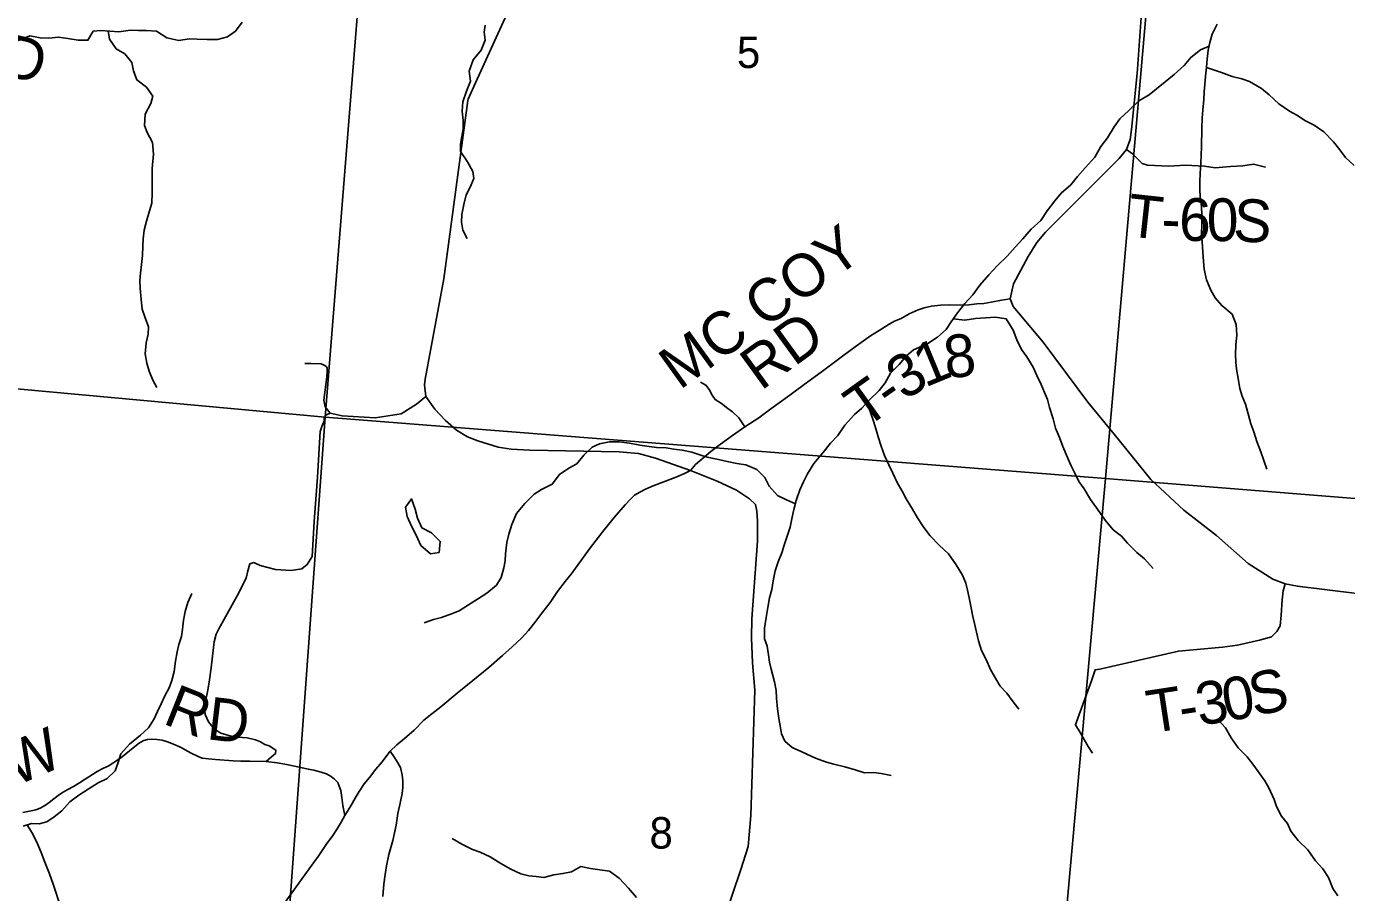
# Model space of a CAD drawing. Extents: x 0 to 42, y 0 to 22.
# Drawn here: x 2.271 to 3.149, y 15.878 to 16.454 of the extents above; entities that cross this region are included whole.
import ezdxf

# ---------------------------------------------------------------- set-up
doc = ezdxf.new("R2010")
doc.units = 0
for name, color, linetype in [('GM_X_County_Road', 7, 'Continuous'), ('GM_X_County_Road_Text', 7, 'Continuous'), ('GM_X_Minor_Lake', 7, 'Continuous'), ('GM_X_Minor_River', 7, 'Continuous'), ('GM_X_Section', 7, 'Continuous'), ('GM_X_Section_Text', 7, 'Continuous'), ('GM_X_Township_Road', 7, 'Continuous'), ('GM_X_Township_Road_Text', 7, 'Continuous'), ('GM_X_Unincorporated', 7, 'Continuous')]:
    doc.layers.add(name, color=color, linetype=linetype)

msp = doc.modelspace()

# ---------------------------------------------------------------- linework, layer by layer
at = {"layer": 'GM_X_County_Road'}
for points in [[(3.15556, 16.07734), (3.11596, 16.08209), (3.10775, 16.08373), (3.09954, 16.08683), (3.08329, 16.09723), (3.06213, 16.11584), (3.04041, 16.13263), (3.01849, 16.15304), (2.99402, 16.18319), (2.97659, 16.20462), (2.94677, 16.24432), (2.92682, 16.26806), (2.92495, 16.27329), (2.92703, 16.28318), (2.9369, 16.30146), (2.94257, 16.3107), (2.94845, 16.31763), (2.99745, 16.36645), (3.0023, 16.37263), (3.00466, 16.37925), (3.00554, 16.38588), (3.00939, 16.42316), (3.01821, 16.54744), (3.01914, 16.57163)], [(2.73394, 15.85903), (2.74582, 15.8937), (2.75074, 15.90912), (2.75254, 15.92978), (2.75503, 16.01291), (2.75344, 16.03129), (2.75281, 16.04777), (2.75312, 16.06045), (2.75693, 16.1121), (2.75685, 16.12533), (2.75653, 16.13198), (2.75558, 16.13642), (2.75146, 16.14022), (2.74291, 16.14593), (2.73008, 16.15195), (2.71233, 16.15915), (2.68905, 16.16732), (2.6778, 16.17033), (2.66481, 16.1716), (2.60551, 16.1727), (2.59308, 16.17332), (2.58439, 16.17456), (2.57093, 16.17871), (2.56409, 16.1814), (2.55664, 16.18595), (2.54937, 16.19225), (2.54217, 16.19996), (2.53637, 16.20835), (2.53544, 16.21601), (2.53591, 16.21985), (2.54815, 16.28662), (2.56429, 16.4051), (2.56443, 16.40592), (2.56825, 16.41433), (2.61413, 16.51522)]]:
    msp.add_lwpolyline(points, dxfattribs=at)
at = {"layer": 'GM_X_Minor_Lake'}
for points in [[(2.52524, 16.13798), (2.52287, 16.13473), (2.52379, 16.12848), (2.52679, 16.12202), (2.52998, 16.11557), (2.53299, 16.1093), (2.5394, 16.10378), (2.54526, 16.10452)], [(2.54526, 16.10452), (2.54586, 16.11191), (2.54002, 16.11761), (2.5336, 16.12105), (2.53078, 16.12731), (2.52929, 16.13338), (2.52686, 16.14021), (2.52524, 16.13798)]]:
    msp.add_lwpolyline(points, dxfattribs=at)
at = {"layer": 'GM_X_Minor_River'}
for points in [[(2.26547, 16.44498), (2.27284, 16.44813), (2.27983, 16.44678), (2.28551, 16.44657), (2.29194, 16.4473), (2.29818, 16.44633), (2.30517, 16.44517), (2.3116, 16.44515), (2.31503, 16.4512), (2.32014, 16.45174), (2.32619, 16.45134), (2.33205, 16.45075), (2.33981, 16.45186), (2.3453, 16.45165), (2.35021, 16.45163), (2.35721, 16.45123), (2.364, 16.44684), (2.37194, 16.44511), (2.37894, 16.44603), (2.38424, 16.44601), (2.39086, 16.44561), (2.39767, 16.44558), (2.4043, 16.44745), (2.4096, 16.45122), (2.41417, 16.45727)], [(2.57569, 16.45533), (2.57511, 16.4506), (2.57566, 16.44529), (2.57317, 16.43867), (2.56785, 16.43206), (2.56518, 16.42468), (2.5661, 16.41804), (2.56343, 16.41123), (2.56094, 16.40423), (2.56054, 16.39798), (2.56108, 16.39191), (2.56106, 16.38604), (2.56029, 16.38111), (2.55932, 16.37619), (2.5593, 16.37127), (2.56401, 16.36443), (2.56758, 16.35797), (2.56832, 16.35323), (2.56584, 16.34756), (2.56317, 16.34245), (2.56163, 16.33601), (2.56028, 16.32939), (2.56008, 16.32427), (2.56081, 16.31896), (2.56382, 16.31327)], [(3.06257, 16.45595), (3.05933, 16.44933), (3.05761, 16.44365), (3.05664, 16.43854), (3.05586, 16.43267), (3.05546, 16.42737), (3.05488, 16.42131), (3.05429, 16.41581), (3.05389, 16.41089), (3.05368, 16.40577), (3.05309, 16.39876), (3.0525, 16.39327), (3.05229, 16.38683), (3.05224, 16.37414), (3.05203, 16.36921), (3.05163, 16.36296), (3.05123, 16.35652), (3.05102, 16.35121), (3.051, 16.3461), (3.05136, 16.34098), (3.05209, 16.33454), (3.05245, 16.32904), (3.05243, 16.3226), (3.05222, 16.31634), (3.05257, 16.31104), (3.05312, 16.30459), (3.05347, 16.29815), (3.05402, 16.29303), (3.05551, 16.28582), (3.05832, 16.27899), (3.06133, 16.27387), (3.06566, 16.26873), (3.07245, 16.26302), (3.07526, 16.25619), (3.07561, 16.24899), (3.07502, 16.24255), (3.07481, 16.23629), (3.07498, 16.23118), (3.07553, 16.22644), (3.07645, 16.22018), (3.07775, 16.21354), (3.07924, 16.20842), (3.0813, 16.20311), (3.08317, 16.19685), (3.08485, 16.19021), (3.08691, 16.18471), (3.08897, 16.17844), (3.09159, 16.17161), (3.09365, 16.16573), (3.09552, 16.16004)], [(2.32494, 16.45143), (2.32598, 16.44585), (2.33031, 16.43958), (2.33616, 16.43615), (2.34068, 16.43045), (2.34179, 16.42495), (2.34404, 16.41888), (2.35045, 16.41392), (2.35478, 16.40804), (2.35344, 16.40311), (2.34963, 16.39612), (2.34922, 16.38854), (2.35091, 16.3838), (2.35448, 16.37715), (2.3552, 16.36938), (2.35422, 16.35991), (2.35418, 16.3493), (2.35435, 16.3438), (2.35414, 16.33679), (2.35242, 16.33168), (2.3505, 16.32487), (2.34896, 16.319), (2.34819, 16.31313), (2.34798, 16.30839), (2.34777, 16.30214), (2.34718, 16.29608), (2.34659, 16.2904), (2.34619, 16.28547), (2.34636, 16.28035), (2.3469, 16.27277), (2.34763, 16.26633), (2.34932, 16.26121), (2.35175, 16.25457), (2.35155, 16.24983), (2.3502, 16.24396), (2.3496, 16.23657), (2.35072, 16.2305), (2.3524, 16.22519), (2.35465, 16.21912), (2.35728, 16.21418)], [(3.05717, 16.44133), (3.05153, 16.43875), (3.04509, 16.43366), (3.04053, 16.42837), (3.03407, 16.42233), (3.028, 16.41743), (3.02231, 16.4129), (3.01738, 16.40894), (3.01036, 16.4048), (3.00372, 16.39838), (2.99784, 16.39291), (2.99403, 16.38762), (2.98966, 16.38025), (2.98528, 16.37458), (2.9811, 16.3674), (2.97483, 16.36041), (2.9697, 16.35455), (2.96533, 16.34908), (2.95888, 16.34342), (2.95451, 16.33832), (2.94956, 16.3317), (2.94519, 16.32528), (2.93893, 16.31962), (2.93323, 16.3132), (2.92829, 16.30753), (2.92297, 16.30168), (2.91652, 16.29545), (2.91082, 16.28922), (2.90474, 16.28223), (2.90018, 16.2758), (2.89467, 16.27014), (2.88992, 16.26391), (2.88574, 16.25805), (2.88231, 16.25294), (2.87662, 16.24766), (2.87017, 16.24352), (2.8607, 16.23938), (2.85596, 16.23542), (2.85102, 16.22957), (2.84532, 16.22371), (2.8417, 16.21728), (2.83771, 16.21218), (2.83107, 16.20577), (2.82632, 16.20048), (2.82139, 16.19633), (2.81493, 16.18934), (2.81036, 16.18235), (2.80543, 16.17725), (2.8003, 16.17083), (2.79422, 16.16365), (2.79003, 16.15684), (2.78736, 16.15155), (2.78507, 16.14625), (2.78259, 16.13906), (2.78105, 16.13319), (2.7799, 16.12808), (2.77855, 16.12145), (2.77683, 16.11615), (2.77453, 16.10953), (2.773, 16.10442), (2.77071, 16.09836), (2.76861, 16.0923), (2.76726, 16.08568), (2.76629, 16.07999), (2.76476, 16.0745), (2.76379, 16.06788), (2.76263, 16.06144), (2.76147, 16.05424), (2.76144, 16.04723), (2.76331, 16.04229), (2.76424, 16.0366), (2.76479, 16.03168), (2.76591, 16.02693), (2.76814, 16.01859), (2.76926, 16.01271), (2.76943, 16.00778), (2.77016, 16.00058), (2.77108, 15.99413), (2.77201, 15.98939), (2.77293, 15.98389), (2.775, 15.97914), (2.7799, 15.97496), (2.78632, 15.97209), (2.79538, 15.96769), (2.80275, 15.9652), (2.80766, 15.96386), (2.81503, 15.96212), (2.82184, 15.96001), (2.82807, 15.9581), (2.83412, 15.95826), (2.83904, 15.95767), (2.84566, 15.95632)], [(3.05543, 16.42699), (3.06548, 16.42373), (3.07247, 16.42105), (3.07889, 16.41951), (3.08399, 16.41778), (3.09211, 16.41302), (3.0972, 16.40883), (3.10361, 16.40293), (3.11059, 16.39798), (3.1155, 16.39531), (3.12135, 16.39168), (3.12701, 16.38882), (3.13342, 16.38425), (3.14002, 16.37759), (3.14416, 16.37227), (3.14793, 16.36733), (3.15377, 16.36181)], [(2.88705, 16.25989), (2.89482, 16.25915), (2.90182, 16.26007), (2.90844, 16.26061), (2.91507, 16.26097), (2.92225, 16.25999), (2.92695, 16.2524), (2.92939, 16.24594), (2.93239, 16.23949), (2.93596, 16.23474), (2.9401, 16.22771), (2.94273, 16.22221), (2.94554, 16.21632), (2.94779, 16.21101), (2.94967, 16.20626), (2.95097, 16.20095), (2.9534, 16.19336), (2.95508, 16.18729), (2.95771, 16.18103), (2.95995, 16.17496), (2.96295, 16.16774), (2.9652, 16.16262), (2.96783, 16.1573), (2.97046, 16.1518), (2.97404, 16.14686), (2.97836, 16.13983), (2.98457, 16.13109), (2.98815, 16.12596), (2.99342, 16.11969), (2.99889, 16.11549), (3.00303, 16.11074), (3.00925, 16.10446), (3.01415, 16.10028), (3.01999, 16.094)], [(2.82967, 16.20421), (2.8318, 16.19837), (2.83404, 16.19192), (2.83572, 16.18623), (2.83722, 16.18149), (2.83909, 16.17523), (2.84134, 16.16915), (2.84415, 16.16289), (2.84697, 16.15738), (2.84978, 16.15112), (2.85316, 16.14542), (2.85579, 16.1403), (2.85993, 16.13327), (2.86331, 16.12757), (2.86707, 16.12187), (2.8714, 16.11579), (2.87762, 16.10951), (2.88384, 16.10362), (2.88892, 16.09639), (2.89325, 16.08956), (2.8955, 16.08424), (2.89661, 16.0795), (2.89773, 16.07438), (2.89866, 16.06888), (2.90014, 16.06205), (2.90107, 16.05731), (2.90387, 16.04593), (2.90573, 16.03929), (2.90893, 16.0334), (2.91193, 16.02676), (2.91456, 16.02201), (2.91832, 16.01574), (2.92265, 16.01099), (2.92623, 16.00624), (2.93056, 16.00035)], [(2.78205, 16.137), (2.77616, 16.13965), (2.77012, 16.14251), (2.76465, 16.1486), (2.76165, 16.15449), (2.75637, 16.15981), (2.74901, 16.16287), (2.74315, 16.16384), (2.73672, 16.165), (2.73086, 16.16635), (2.72349, 16.16789), (2.71858, 16.16943), (2.71329, 16.17134), (2.70667, 16.17251), (2.70119, 16.17329), (2.69609, 16.17425), (2.68966, 16.17428), (2.68474, 16.17505), (2.6785, 16.17602), (2.6717, 16.17719), (2.66489, 16.17816), (2.65846, 16.17818), (2.65184, 16.17688), (2.64691, 16.17463), (2.6414, 16.16934), (2.63665, 16.16349), (2.63135, 16.16066), (2.62509, 16.15652), (2.62034, 16.1499), (2.61332, 16.14652), (2.60839, 16.14332), (2.60213, 16.13709), (2.59662, 16.13048), (2.59357, 16.12328), (2.59146, 16.11685), (2.59012, 16.11117), (2.58933, 16.10378), (2.58894, 16.09905), (2.58816, 16.09431), (2.58644, 16.08788), (2.5832, 16.08277), (2.57675, 16.07749), (2.57068, 16.07353), (2.56462, 16.06977), (2.55836, 16.06581), (2.55344, 16.06374), (2.54681, 16.06131), (2.54132, 16.06), (2.53525, 16.05775)], [(2.26843, 15.92269), (2.27411, 15.92437), (2.27922, 15.92416), (2.28414, 15.92547), (2.28907, 15.92886), (2.29419, 15.93282), (2.29951, 15.93887), (2.30558, 15.9432), (2.31165, 15.94716), (2.31828, 15.95149), (2.32435, 15.95431), (2.32966, 15.95941), (2.33158, 15.9649), (2.33349, 15.97058), (2.33919, 15.97719), (2.34659, 15.98303), (2.3519, 15.98794), (2.35552, 15.99399), (2.3578, 15.99891), (2.36028, 16.00383), (2.36276, 16.00932), (2.36562, 16.01461), (2.36734, 16.01953), (2.36887, 16.0254), (2.36984, 16.03222), (2.37081, 16.03847), (2.37197, 16.04339), (2.37369, 16.04869), (2.37446, 16.05362), (2.37505, 16.05949), (2.37621, 16.06536), (2.37793, 16.07123), (2.3806, 16.07728)], [(3.14289, 15.87616), (3.13951, 15.8811), (3.13651, 15.8885), (3.13275, 15.8942), (3.12804, 15.89953), (3.12296, 15.90675), (3.11636, 15.91303), (3.11165, 15.9193), (3.1094, 15.92442), (3.10545, 15.92918), (3.10207, 15.93563), (3.10057, 15.94038), (3.09682, 15.94797), (3.09419, 15.95272), (3.08986, 15.95899), (3.08628, 15.96374), (3.08252, 15.96868), (3.07649, 15.97458), (3.07197, 15.98142), (3.06821, 15.98788), (3.06313, 15.9934)], [(2.27116, 15.92349), (2.27428, 15.9183), (2.27766, 15.91185), (2.28047, 15.90502), (2.28291, 15.89856), (2.28609, 15.89078), (2.28834, 15.88395), (2.29021, 15.87864), (2.29171, 15.87371), (2.29677, 15.86175), (2.29921, 15.85586), (2.30183, 15.84941), (2.30484, 15.84428), (2.31069, 15.84066), (2.31672, 15.83438), (2.31783, 15.82794), (2.31819, 15.82244), (2.31836, 15.81732), (2.31947, 15.81106), (2.32323, 15.80631)], [(2.67644, 15.8751), (2.67098, 15.88137), (2.66495, 15.88803), (2.65854, 15.8926), (2.65211, 15.89357), (2.64587, 15.89454), (2.63944, 15.8957), (2.63319, 15.89232), (2.62751, 15.89101), (2.62146, 15.89028), (2.61483, 15.88841), (2.60972, 15.88918), (2.60481, 15.88958), (2.59952, 15.89093), (2.59291, 15.89399), (2.58611, 15.8978), (2.57913, 15.90219), (2.57252, 15.90524), (2.56723, 15.90697), (2.56025, 15.9106), (2.55383, 15.91441)]]:
    msp.add_lwpolyline(points, dxfattribs=at)
at = {"layer": 'GM_X_Section'}
for points in [[(2.58086, 16.73111), (3.03461, 16.68491), (2.98825, 16.15388), (2.46933, 16.19453), (2.51268, 16.73806)], [(3.48448, 16.64214), (3.5233, 16.63832), (3.48071, 16.11423), (2.98825, 16.15388), (3.03461, 16.68491)], [(2.46933, 16.19453), (2.98825, 16.15388), (2.9429, 15.65088), (2.43288, 15.69341)], [(2.98825, 16.15388), (3.48071, 16.11423), (3.44005, 15.61015), (2.9429, 15.65088)]]:
    msp.add_lwpolyline(points, close=True, dxfattribs=at)
at = {"layer": 'GM_X_Township_Road'}
for points in [[(3.0023, 16.37263), (3.00628, 16.36969), (3.0126, 16.36321), (3.01613, 16.36218), (3.03012, 16.36145), (3.04159, 16.36218), (3.05411, 16.36145), (3.06117, 16.36042), (3.07147, 16.3613), (3.07957, 16.36159), (3.08663, 16.36277), (3.09472, 16.36071)], [(2.74852, 16.18812), (2.75772, 16.19421), (2.76567, 16.20006), (2.77836, 16.20926), (2.78793, 16.21622), (2.79912, 16.22443), (2.81417, 16.23574), (2.82424, 16.24308), (2.83195, 16.24867), (2.83779, 16.25215), (2.8445, 16.25638), (2.84799, 16.25849), (2.85234, 16.26011), (2.85781, 16.26334), (2.86365, 16.26595), (2.86776, 16.2672), (2.87248, 16.26844), (2.87857, 16.26894), (2.88442, 16.26919), (2.892, 16.26906), (2.89747, 16.26931), (2.90269, 16.26981), (2.9073, 16.27006), (2.91227, 16.27105), (2.91923, 16.2723), (2.92495, 16.27329)], [(2.47262, 16.19721), (2.46933, 16.20142), (2.46853, 16.20576), (2.47037, 16.22142), (2.47069, 16.22478), (2.47061, 16.22735), (2.47005, 16.22823), (2.46901, 16.22895), (2.4666, 16.23), (2.46009, 16.23015), (2.45585, 16.2302)], [(2.74852, 16.18812), (2.74615, 16.19135), (2.74441, 16.19409), (2.74019, 16.19819), (2.7372, 16.2003), (2.73285, 16.20354), (2.72862, 16.20627), (2.72663, 16.20913), (2.72464, 16.21286), (2.72253, 16.21585), (2.71895, 16.21776)], [(2.46722, 16.18826), (2.4686, 16.19216), (2.46873, 16.19452), (2.47023, 16.19616), (2.47262, 16.19721), (2.48072, 16.19541), (2.5026, 16.19403), (2.51978, 16.19673), (2.53011, 16.20327), (2.53637, 16.20835)], [(2.45513, 16.09474), (2.45738, 16.09661), (2.4608, 16.10182), (2.46192, 16.12524), (2.46425, 16.15476), (2.46603, 16.18492), (2.46722, 16.18826)], [(2.71233, 16.15915), (2.71569, 16.163), (2.72129, 16.16785), (2.72576, 16.17183), (2.73223, 16.17656), (2.74019, 16.1824), (2.74852, 16.18812)], [(2.5126, 15.97237), (2.517, 15.97662), (2.5221, 15.98085), (2.52844, 15.98644), (2.53503, 15.99303), (2.54038, 15.99739), (2.54634, 16.00186), (2.55704, 16.01106), (2.56748, 16.01939), (2.57817, 16.0281), (2.58725, 16.03618), (2.59372, 16.04177), (2.59993, 16.04749), (2.60466, 16.05272), (2.60876, 16.05806), (2.61349, 16.06415), (2.61896, 16.07137), (2.62393, 16.07858), (2.62903, 16.08529), (2.63288, 16.09014), (2.63761, 16.09661), (2.64581, 16.10792), (2.65489, 16.11961), (2.6626, 16.12918), (2.66907, 16.13639), (2.67217, 16.13988), (2.67516, 16.14274), (2.67864, 16.1446), (2.68237, 16.14659), (2.68747, 16.14883), (2.69567, 16.15206), (2.70326, 16.15492), (2.70836, 16.15703), (2.71233, 16.15915)], [(2.43004, 15.96559), (2.43363, 15.96879), (2.43637, 15.9709), (2.43649, 15.97314), (2.432, 15.97596), (2.42928, 15.97687), (2.42642, 15.97861), (2.42306, 15.97998), (2.41747, 15.98122), (2.40839, 15.98197), (2.39994, 15.98445), (2.39571, 15.98719), (2.39186, 15.99191), (2.38962, 15.99676), (2.389, 16.00186), (2.38999, 16.00659), (2.39111, 16.01181), (2.39223, 16.01827), (2.39347, 16.02785), (2.39434, 16.03556), (2.39546, 16.04526), (2.39683, 16.05023), (2.39869, 16.05371), (2.41088, 16.07584), (2.41672, 16.08741), (2.41797, 16.09238), (2.41921, 16.09698), (2.42194, 16.09797), (2.42605, 16.09598), (2.43624, 16.09325), (2.44681, 16.0925), (2.45377, 16.09362), (2.45513, 16.09474)], [(3.10775, 16.08373), (3.10647, 16.07898), (3.10574, 16.07314), (3.10519, 16.06293), (3.10446, 16.05581), (3.10227, 16.05198), (3.09862, 16.04851), (3.09078, 16.04632), (3.07618, 16.04304), (3.06614, 16.04158), (3.03676, 16.03902), (2.98449, 16.02694), (2.98153, 16.02655), (2.97891, 16.01933), (2.96985, 15.99429), (2.96825, 15.9899), (2.97135, 15.98478), (2.97687, 15.97566), (2.97963, 15.9711)], [(2.26821, 15.93176), (2.27158, 15.9323), (2.27381, 15.93277), (2.27684, 15.93344), (2.27981, 15.93466), (2.28325, 15.93661), (2.28588, 15.93836), (2.28898, 15.94086), (2.29255, 15.94369), (2.29512, 15.94524), (2.29815, 15.94686), (2.302, 15.94902), (2.30597, 15.95145), (2.30968, 15.95387), (2.31454, 15.95698), (2.31778, 15.959), (2.32182, 15.96109), (2.32492, 15.96257), (2.32823, 15.96446), (2.33072, 15.96615), (2.33436, 15.96871), (2.33915, 15.97276), (2.34286, 15.97552), (2.34596, 15.97802), (2.34866, 15.9795), (2.35129, 15.98017), (2.35405, 15.98038), (2.35729, 15.98031), (2.36093, 15.97977), (2.36451, 15.97862), (2.36849, 15.97707), (2.37348, 15.97491), (2.37624, 15.97343), (2.38015, 15.9712), (2.38487, 15.96884), (2.38757, 15.96783), (2.39175, 15.96729), (2.39634, 15.96689), (2.4082, 15.96601), (2.41326, 15.96588), (2.41926, 15.96574), (2.43004, 15.96559)], [(2.48243, 15.92975), (2.48641, 15.93609), (2.48927, 15.94131), (2.49188, 15.94566), (2.49524, 15.95063), (2.49872, 15.95499), (2.50307, 15.96058), (2.50718, 15.96531), (2.51029, 15.96966), (2.5126, 15.97237)], [(2.5126, 15.97237), (2.51538, 15.96829), (2.51762, 15.96468), (2.51949, 15.9617), (2.52061, 15.95673), (2.52098, 15.95275), (2.5211, 15.94827), (2.52048, 15.94429), (2.51924, 15.93783), (2.51775, 15.93099), (2.5165, 15.92328), (2.51426, 15.91296), (2.51178, 15.90376), (2.51016, 15.89617), (2.50929, 15.89046), (2.50842, 15.88399), (2.50768, 15.87578)], [(2.43004, 15.96559), (2.43735, 15.9648), (2.44251, 15.96391), (2.45109, 15.96195), (2.45813, 15.96054), (2.46175, 15.95974), (2.4666, 15.95846), (2.47018, 15.95731), (2.47328, 15.95563), (2.47557, 15.95374), (2.47766, 15.95151), (2.47874, 15.94929), (2.47968, 15.94619), (2.48036, 15.94167), (2.48103, 15.93642), (2.48243, 15.92975)], [(2.44276, 15.87215), (2.45407, 15.88776), (2.46054, 15.89668), (2.46465, 15.90247), (2.47, 15.91035), (2.47435, 15.91632), (2.47734, 15.92092), (2.48007, 15.92527), (2.48243, 15.92975)]]:
    msp.add_lwpolyline(points, dxfattribs=at)
at = {"layer": 'GM_X_Unincorporated'}
for points in [[(2.1, 16.77811), (2.1, 16.22845), (2.46933, 16.19453), (2.51268, 16.73806)], [(2.1, 16.22845), (2.1, 15.71754), (2.43288, 15.69341), (2.46933, 16.19453)]]:
    msp.add_lwpolyline(points, close=True, dxfattribs=at)

# ---------------------------------------------------------------- texts
at = {"layer": 'GM_X_County_Road_Text'}
msp.add_text('D', height=0.02841, rotation=347.29646, dxfattribs=at).set_placement((2.25331, 16.42208))
at = {"layer": 'GM_X_Section_Text'}
for s, p in [('5', (2.74314, 16.42669)), ('8', (2.68502, 15.90768))]:
    msp.add_text(s, height=0.02093, rotation=0.00001, dxfattribs=at).set_placement(p)
at = {"layer": 'GM_X_Township_Road_Text'}
for s, height, rotation, p in [('T', 0.02841, 353.77812, (3.00177, 16.315)), ('6', 0.02841, 357.99601, (3.03683, 16.31213)), ('0', 0.02841, 0.71124, (3.05579, 16.3115)), ('S', 0.02841, 356.68153, (3.07276, 16.31173)), ('MC COY', 0.028409, 35.7825, (2.70505, 16.21222)), ('-', 0.02841, 358.00666, (3.02517, 16.31253)), ('RD', 0.028409, 35.99155, (2.75914, 16.21174)), ('1', 0.02841, 22.37928, (2.86813, 16.21407)), ('8', 0.02841, 5.93791, (2.88223, 16.2202)), ('3', 0.02841, 32.76774, (2.85462, 16.20523)), ('T', 0.02841, 35.61838, (2.82813, 16.18633)), ('-', 0.02841, 35.22097, (2.84536, 16.19868)), ('S', 0.02841, 12.74804, (3.08721, 15.99539)), ('R', 0.02841, 338.29499, (2.3606, 15.99111)), ('T', 0.02841, 8.71619, (3.018, 15.98426)), ('3', 0.02841, 9.03125, (3.0507, 15.98929)), ('0', 0.02841, 9.79812, (3.0684, 15.9921)), ('D', 0.02841, 353.16025, (2.38992, 15.98053)), ('-', 0.02841, 8.77123, (3.03904, 15.98748)), ('W', 0.02841, 23.10983, (2.26323, 15.94892))]:
    msp.add_text(s, height=height, rotation=rotation, dxfattribs=at).set_placement(p)

doc.saveas('drawing.dxf')
